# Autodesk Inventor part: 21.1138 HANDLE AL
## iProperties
Created: 2007-02
Part Number: 21.1138 HANDLE AL
Document SubType Name: Modeling
Designer: Andy Moles
Material: Aluminum-6061
Density: 2.71 g/cm^3
Author: Andy Moles
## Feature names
1. Extrusion1
2. Revolution1
3. Revolution2
4. Extrusion2
5. Extrusion3
6. Extrusion4
7. Extrusion5
